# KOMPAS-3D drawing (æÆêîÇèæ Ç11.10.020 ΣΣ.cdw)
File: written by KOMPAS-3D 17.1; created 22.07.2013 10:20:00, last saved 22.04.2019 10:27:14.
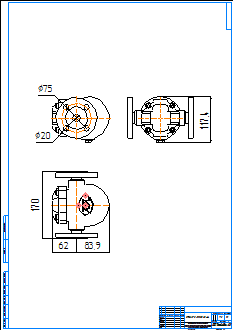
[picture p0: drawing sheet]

Sheet 1: A1, portrait

Title block, sheet 1: name: СТИМАКС А11.10.020 фф; material: Внимание! Данный продукт является объектом авторского права ООО «Торговый Дом АДЛ». / Запрещается изменение, копирование, распространение / (в том числе путем копирования на другие сайты и ресурсы в Интернете) / или любое иное использование информации и объектов без предварительного / согласия правообладателя (ООО «Торговый Дом АДЛ»).; mass: 7,5; sheets: 1; organisation: ООО "Торговый дом АДЛ"; sheet format: A1; stored path: \\adlc.lan\data\АДЛ_ПКД\3D-модели\ADL production\Конденсатоотводчики СТИМАКС\Поплавковые\Серия А11\KOMPAS 2D\СТИМАКС А11.10.020 фф.cdw

Views: Вид 1, Проекционный вид 2
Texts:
  Klimkovich
  ADL
Dimensions and other numbers on the sheet: 20; 170; 62; 83,9; 1:1; 1; 7,5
